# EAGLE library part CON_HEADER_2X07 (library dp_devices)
2x07 pin header
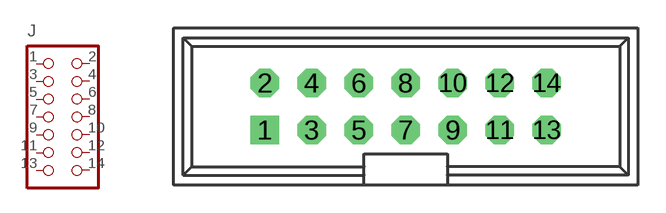
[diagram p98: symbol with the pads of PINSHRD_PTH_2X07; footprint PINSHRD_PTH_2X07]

Designator prefix J

## CON_HEADER_2X07-PTH-SHROUDED  [PINSHRD_PTH_2X07]
1  1  pas
2  2  pas
3  3  pas
4  4  pas
5  5  pas
6  6  pas
7  7  pas
8  8  pas
9  9  pas
10  10  pas
11  11  pas
12  12  pas
13  13  pas
14  14  pas

## Footprint PINSHRD_PTH_2X07 (pad centres in mm)
Shrouded pin header, 0.1" pitch
drill 1.016 square: 1 -7.62,-1.27
drill 1.016 octagon: 2 -7.62,1.27; 3 -5.08,-1.27; 4 -5.08,1.27; 5 -2.54,-1.27; 6 -2.54,1.27; 7 0,-1.27; 8 0,1.27; 9 2.54,-1.27; 10 2.54,1.27; 11 5.08,-1.27; 12 5.08,1.27; 13 7.62,-1.27; 14 7.62,1.27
